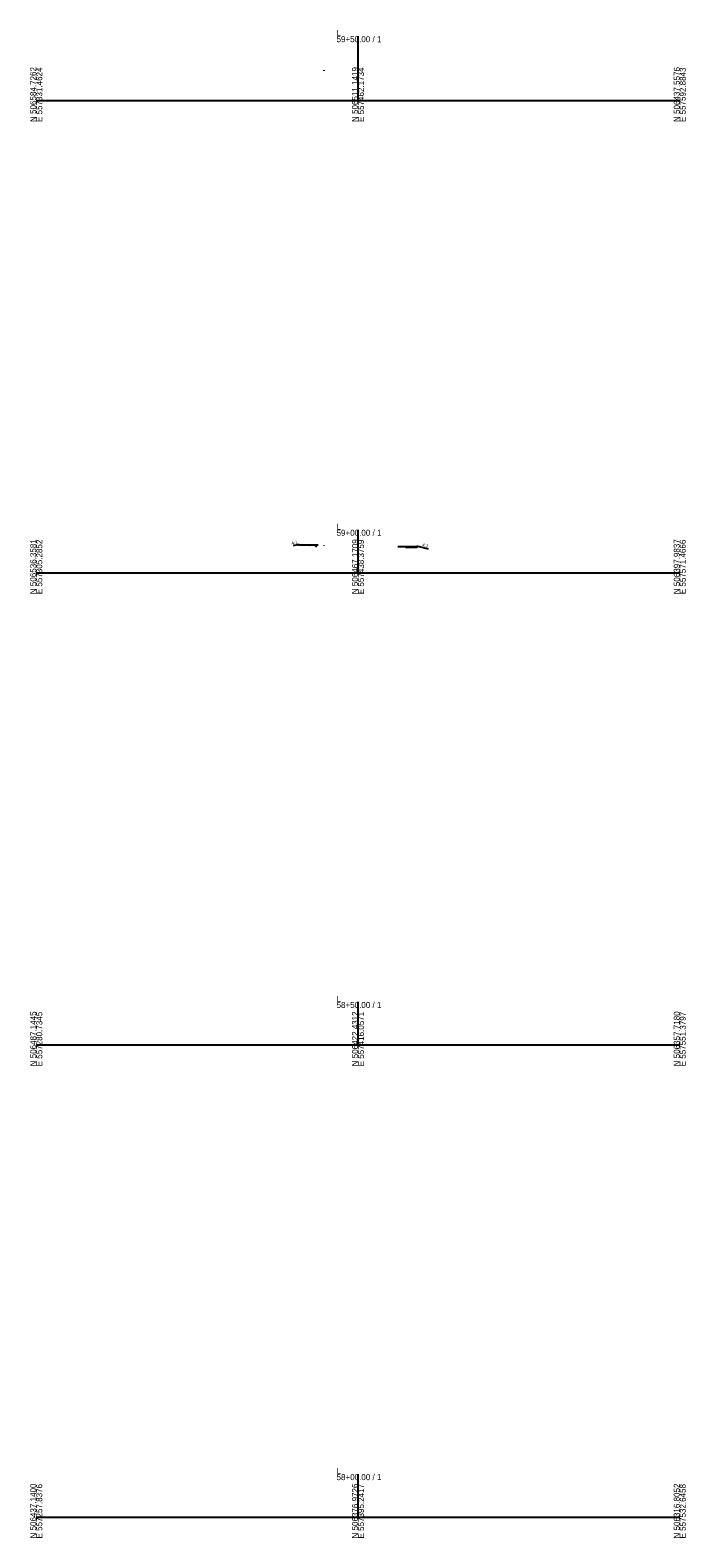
# Model space of a CAD drawing. Extents: x -26 to 3303, y -10 to 4703.
# Drawn here: x 1997 to 2303, y 3645 to 4348 of the extents above; entities that cross this region are included whole.
import ezdxf

# ---------------------------------------------------------------- set-up
doc = ezdxf.new("R2010")
doc.units = 0
for name, color, linetype in [('Exist Cross Section Cell', 7, 'Continuous'), ('Scratch_Level_0', 7, 'Continuous'), ('Scratch_Level_9', 7, 'Continuous')]:
    doc.layers.add(name, color=color, linetype=linetype)

msp = doc.modelspace()

# ---------------------------------------------------------------- linework, layer by layer
at = {"layer": 'Exist Cross Section Cell'}
for p, q in [((2150, 4315), (2150, 4345)), ((2000, 4315), (2150, 4315)), ((2150, 4315), (2300, 4315)), ((2150, 4095), (2150, 4115)), ((2000, 4095), (2150, 4095)), ((2150, 4095), (2300, 4095)), ((2150, 3875), (2150, 3895)), ((2000, 3875), (2150, 3875)), ((2150, 3875), (2300, 3875)), ((2150, 3655), (2150, 3675)), ((2000, 3655), (2150, 3655)), ((2150, 3655), (2300, 3655))]:
    msp.add_line(p, q, dxfattribs=at)
at = {"layer": 'Scratch_Level_0'}
for points in [[(2119.97, 4107.64), (2122, 4108.15), (2122, 4108.15)], [(2122, 4108.15), (2122, 4108.15), (2122.5, 4108.14)], [(2122.5, 4108.14), (2127.5, 4108.04), (2127.5, 4108.04), (2127.51, 4107.7), (2122.49, 4107.8), (2122.49, 4107.8), (2122.5, 4108.14), (2122.5, 4108.14), (2122.5, 4108.14)], [(2127.5, 4108.04), (2127.5, 4108.04), (2131.5, 4107.96)], [(2129.71, 4107.99), (2129.71, 4107.99), (2130.7, 4107)], [(2172.5, 4107.08), (2172.5, 4107.08), (2168.5, 4107)], [(2177.5, 4107.18), (2172.5, 4107.08), (2172.5, 4107.08), (2172.49, 4106.74), (2177.51, 4106.84), (2177.51, 4106.84), (2177.5, 4107.18), (2177.5, 4107.18), (2177.5, 4107.18)], [(2178, 4107.19), (2178, 4107.19), (2177.5, 4107.18)], [(2182.94, 4105.95), (2178, 4107.19), (2178, 4107.19)]]:
    msp.add_lwpolyline(points, dxfattribs=at)
at = {"layer": 'Scratch_Level_9'}
for points in [[(2134, 4329.16), (2134, 4328.91)], [(2134, 4107.86), (2134, 4107.61)]]:
    msp.add_lwpolyline(points, dxfattribs=at)

# ---------------------------------------------------------------- texts
at = {"layer": 'Exist Cross Section Cell'}
for s, p in [('59+50.00 / 1', (2140, 4342.2)), ('L', (2140, 4345)), ('L', (2140, 4115)), ('59+00.00 / 1', (2140, 4112.2)), ('58+50.00 / 1', (2140, 3892.2)), ('L', (2140, 3895)), ('58+00.00 / 1', (2140, 3672.2)), ('L', (2140, 3675))]:
    msp.add_text(s, height=2.8, dxfattribs=at).set_placement(p)
for s, p in [('N 506584.7262', (2000, 4305)), ('E 557331.4624', (2002.8, 4305)), ('N 506511.1419', (2150, 4305)), ('E 557462.1734', (2152.8, 4305)), ('N 506437.5576', (2300, 4305)), ('E 557592.8843', (2302.8, 4305)), ('N 506536.3581', (2000, 4085)), ('E 557305.2852', (2002.8, 4085)), ('N 506467.1709', (2150, 4085)), ('E 557438.3759', (2152.8, 4085)), ('N 506397.9837', (2300, 4085)), ('E 557571.4666', (2302.8, 4085)), ('N 506487.1445', (2000, 3865)), ('E 557280.7345', (2002.8, 3865)), ('N 506422.4312', (2150, 3865)), ('E 557416.0571', (2152.8, 3865)), ('N 506357.7180', (2300, 3865)), ('E 557551.3797', (2302.8, 3865)), ('N 506437.1400', (2000, 3645)), ('E 557257.8376', (2002.8, 3645)), ('N 506376.9726', (2150, 3645)), ('E 557395.2417', (2152.8, 3645)), ('N 506316.8052', (2300, 3645)), ('E 557532.6458', (2302.8, 3645))]:
    msp.add_text(s, height=2.8, rotation=90, dxfattribs=at).set_placement(p)
at = {"layer": 'Scratch_Level_0'}
for rotation, p in [(14.03624, (2119.15, 4107.92)), (345.96376, (2179.8, 4107.34))]:
    msp.add_text('4:1', height=1.5, rotation=rotation, dxfattribs=at).set_placement(p)
for p in [(2119.97, 4107.64), (2122, 4108.14), (2122.5, 4108.13), (2127.5, 4108.03), (2172.5, 4107.07), (2177.5, 4107.17), (2178, 4107.18)]:
    msp.add_text('X', height=0.0025, dxfattribs=at).set_placement(p)

doc.saveas('drawing.dxf')
